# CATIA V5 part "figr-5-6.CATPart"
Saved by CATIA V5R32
Part number: Part1
Bounding box of the stored display mesh (mm): x 0 to 150, y -70 to 70, z -150 to 69.804
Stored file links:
  D:\PROJECTS\Project 2022\CATIA V5 6R 2022\Resources\Part Files\c05_catia_v5_6r2022_prt\figr-5-6.CATPart
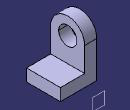
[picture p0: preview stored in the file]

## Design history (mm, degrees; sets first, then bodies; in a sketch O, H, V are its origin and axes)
Set1
  Plane1: type Offset, RefPlane face of Pad2, Offset 79, reversed
Body1 (main body)
  Sketch1 on yz-plane, origin (0, 0, 0), H (0, 1, 0), V (0, 0, 1)
    arc A1 centre (0, 0) radius 70 from (70, 0) to (-70, 0) ccw
    point P1 (70, 0)
    point P2 (-70, 0)
    line L1 (-70, 0) -> (-70, -150)
    line L2 (-70, -150) -> (70, -150)
    line L3 (70, -150) -> (70, 0)
    circle A2 centre (0, 0) radius 37.5
    radius A1 = 70
    radius A2 = 37.5
    distance O L2 = 150
    coincidence: P1 H, P2 H
    tangency: L1 A1, L3 A1
    horizontal: L2 H
  Pad1: profile Sketch1, direction (1, 0, 0), length 50
  Sketch2 on face of Pad1, origin (50, 0, 0), H (0, 1, 0), V (0, 0, 1)
    line L1 (-70, -150) -> (70, -150)
    line L2 (70, -150) -> (70, -100)
    line L3 (70, -100) -> (-70, -100)
    line L4 (-70, -100) -> (-70, -150)
    reference projected line E1 (-70, -150) -> (70, -150) from edge [face of Pad1 | face of Pad1]
    reference projected line E2 (-70, 0) -> (-70, -150) from edge [face of Pad1 | face of Pad1]
    reference projected line E3 (70, -150) -> (70, 0) from edge [face of Pad1 | face of Pad1]
    length L2 = 50
    horizontal: L1 H, L3 H
    vertical: L2 V, L4 V
    coincidence: L1 E1, E2 L4, L2 E3
  Pad2: profile Sketch2, direction (1, 0, 0), length 100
